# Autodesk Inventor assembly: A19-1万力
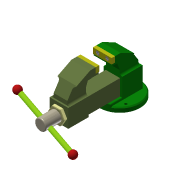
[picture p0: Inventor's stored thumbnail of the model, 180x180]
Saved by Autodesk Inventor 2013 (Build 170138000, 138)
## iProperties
Created: 2008-07
Part Number: A19-1万力
Document SubType Name: Assembly
Designer: y-shimohigashi
Stock Number: A19-1万力
ドキュメント番号: 19
目的: プロパティコピー練習
Author: y-shimohigashi
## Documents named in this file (5)
- C:\Users\t-komatsu\Desktop\新しいフォルダー\Inventor2013基礎コース\練習問題-19\A19-1万力.iam
- C:\Users\t-komatsu\Desktop\新しいフォルダー\Inventor2013基礎コース\練習問題-19\A19-8ハンドル部.iam
- C:\Users\t-komatsu\Desktop\新しいフォルダー\Inventor2013基礎コース\練習問題-19\A19-12.iam
- C:\Users\t-komatsu\Desktop\新しいフォルダー\Inventor2013基礎コース\練習問題-19\A19-13.iam
- C:\Users\t-komatsu\Desktop\新しいフォルダー\Inventor2013基礎コース\練習問題-19\A19-14.iam
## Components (4 placed, 4 different names)
1. A19-12:1 [sub-assembly] — メイト:5, メイト:6, メイト:7
2. A19-8ハンドル部:1 [sub-assembly] — メイト:8, メイト:9
3. A19-13:1 [sub-assembly] — メイト:5, メイト:6, メイト:7, 挿入:1
4. A19-14:1 [sub-assembly] — 挿入:1, メイト:8, メイト:9
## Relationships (6: Mate 5, Insert 1)
- メイト:5 [Mate]: A19-12:1 ↔ A19-13:1
- メイト:6 [Mate]: A19-12:1 ↔ A19-13:1
- メイト:7 [Mate]: A19-12:1 ↔ A19-13:1
- 挿入:1 [Insert]: A19-13:1 ↔ A19-14:1
- メイト:8 [Mate]: A19-8ハンドル部:1 ↔ A19-14:1
- メイト:9 [Mate]: A19-8ハンドル部:1 ↔ A19-14:1
